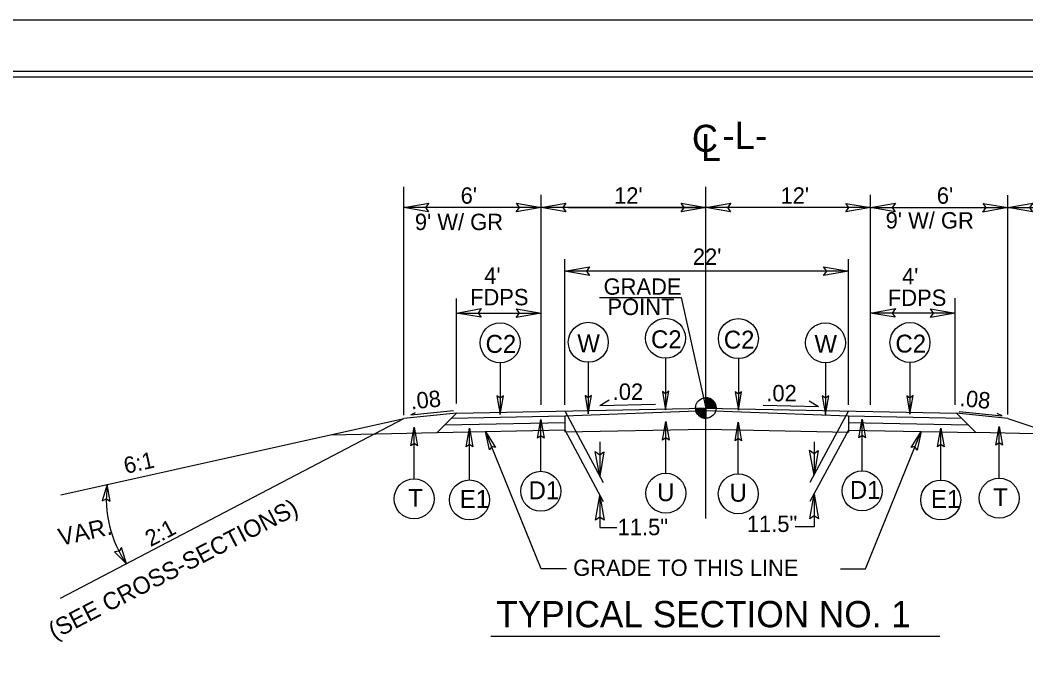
# Model space of a CAD drawing. Extents: x 1718167 to 1721223, y 797898 to 799800.
# Drawn here: x 1719514 to 1719953.6, y 798840.7 to 799124.4 of the extents above; entities that cross this region are included whole.
import ezdxf

# ---------------------------------------------------------------- set-up
doc = ezdxf.new("R2010")
doc.units = 0
for name, color, linetype in [('Old_Level_1', 7, 'Continuous'), ('Old_Level_2', 7, 'Continuous'), ('Prop Dimension Text', 7, 'Continuous'), ('Prop Terminator CELL', 7, 'Continuous'), ('Sheet Cutting Line CELL', 7, 'Continuous'), ('Sheet Plot Border Inside CELL', 7, 'Continuous'), ('Sheet Plot Border Outside CELL', 7, 'Continuous'), ('Sheet Typical CELL', 7, 'Continuous'), ('Typical ID Circle CELL', 7, 'Continuous'), ('Typical Slope Point Local CELL', 7, 'Continuous'), ('Typical Terminator CELL', 7, 'Continuous'), ('Typical Text Centerline CELL', 7, 'Continuous'), ('Typical Text Grade Point CELL', 7, 'Continuous'), ('Typical Text ID Circle CELL', 7, 'Continuous'), ('Typical Text Label CELL', 7, 'Continuous')]:
    doc.layers.add(name, color=color, linetype=linetype)

# ---------------------------------------------------------------- blocks, each defined once
blk = doc.blocks.new('TERMINATOR')
at = {"layer": 'Typical Terminator CELL'}
blk.add_lwpolyline([(-0.469, 0.081), (0, 0), (-0.471, -0.083), (-0.411, 0)], close=True, dxfattribs=at)

msp = doc.modelspace()

# ---------------------------------------------------------------- linework, layer by layer
at = {"layer": 'Old_Level_1'}
for p, q in [((1719681.71, 798951.59), (1719681.73, 799051.4)), ((1719741.7, 798956.19), (1719741.72, 799047.93)), ((1719885.7, 798956.16), (1719885.72, 799047.9)), ((1719945.7, 798951.89), (1719945.72, 799047.89)), ((1719741.72, 799042.41), (1719681.72, 799042.43)), ((1719813.72, 799042.4), (1719741.72, 799042.41)), ((1719753.72, 799042.41), (1719813.72, 799042.4)), ((1719885.72, 799042.38), (1719813.72, 799042.4)), ((1719885.72, 799042.38), (1720017.84, 799042.36)), ((1719752.01, 798989.24), (1719752.01, 799019.85)), ((1719876.01, 798989.22), (1719876.01, 799019.82)), ((1719876.01, 799014.6), (1719752.01, 799014.63)), ((1719704.7, 798956.67), (1719704.71, 799002.7)), ((1719767.28, 799003.14), (1719802.96, 799003.13)), ((1719802.96, 799003.13), (1719813.7, 798954.76)), ((1719922.7, 798956.15), (1719922.71, 799002.82)), ((1719704.71, 798996.29), (1719741.71, 798996.29)), ((1719922.71, 798996.28), (1719885.71, 798996.29)), ((1719752, 798956.19), (1719752.01, 798989.24)), ((1719876, 798956.16), (1719876.01, 798989.22)), ((1719813.7, 798954.76), (1719813.71, 798959.26)), ((1719752, 798953.47), (1719768.77, 798922.18)), ((1719809.2, 798954.76), (1719813.7, 798954.76)), ((1719813.69, 798950.26), (1719813.7, 798954.76)), ((1719813.7, 798954.76), (1719813.69, 798950.26)), ((1719818.2, 798954.76), (1719813.7, 798954.76)), ((1719876, 798953.46), (1719859.24, 798922.16)), ((1719924.47, 798953.28), (1719943.19, 798951.38)), ((1719704.71, 798952.49), (1719681.7, 798950.17)), ((1719945.7, 798950.2), (1719923.24, 798952.48)), ((1719943.19, 798951.38), (1719941.11, 798952.42)), ((1719945.7, 798950.2), (1720017.82, 798926.14)), ((1719741.69, 798884.42), (1719717.44, 798944.48)), ((1719752, 798945.15), (1719768.76, 798913.86)), ((1719876, 798945.14), (1719859.23, 798913.84)), ((1719883.54, 798884.42), (1719907.79, 798944.48)), ((1719767.32, 798939.93), (1719767.32, 798924.87)), ((1719860.99, 798939.93), (1719860.99, 798925.45)), ((1719767.32, 798916.55), (1719767.32, 798902.47)), ((1719860.99, 798917.13), (1719860.99, 798902.83)), ((1719767.32, 798902.47), (1719774.83, 798902.47)), ((1719860.99, 798902.83), (1719852.72, 798902.83)), ((1719752.74, 798884.42), (1719741.69, 798884.42)), ((1719872.5, 798884.42), (1719883.54, 798884.42))]:
    msp.add_line(p, q, dxfattribs=at)
for points in [[(1719813.75, 798959.26), (1719813.75, 798959.26), (1719813.74, 798954.76)], [(1719813.84, 798959.26), (1719813.83, 798954.76)], [(1719813.93, 798959.25), (1719813.92, 798954.76)], [(1719814.02, 798959.25), (1719814.01, 798954.76)], [(1719814.11, 798959.24), (1719814.1, 798954.76)], [(1719814.2, 798959.23), (1719814.19, 798954.76)], [(1719814.29, 798959.22), (1719814.28, 798954.76)], [(1719814.38, 798959.21), (1719814.37, 798954.76)], [(1719814.47, 798959.2), (1719814.46, 798954.76)], [(1719814.56, 798959.18), (1719814.55, 798954.76)], [(1719814.65, 798959.16), (1719814.64, 798954.76)], [(1719814.74, 798959.14), (1719814.73, 798954.76)], [(1719814.83, 798959.12), (1719814.82, 798954.76)], [(1719814.92, 798959.09), (1719814.91, 798954.76)], [(1719815.01, 798959.07), (1719815, 798954.76)], [(1719815.1, 798959.04), (1719815.09, 798954.76)], [(1719815.19, 798959.01), (1719815.18, 798954.76)], [(1719815.28, 798958.98), (1719815.27, 798954.76)], [(1719815.37, 798958.94), (1719815.36, 798954.76)], [(1719815.46, 798958.9), (1719815.45, 798954.76)], [(1719815.55, 798958.86), (1719815.54, 798954.76)], [(1719815.64, 798958.82), (1719815.63, 798954.76)], [(1719815.73, 798958.78), (1719815.72, 798954.76)], [(1719815.82, 798958.73), (1719815.81, 798954.76)], [(1719815.91, 798958.68), (1719815.9, 798954.76)], [(1719816, 798958.63), (1719815.99, 798954.76)], [(1719816.09, 798958.58), (1719816.08, 798954.76)], [(1719816.18, 798958.52), (1719816.17, 798954.76)], [(1719816.27, 798958.46), (1719816.26, 798954.76)], [(1719816.36, 798958.39), (1719816.35, 798954.76)], [(1719816.45, 798958.33), (1719816.44, 798954.76)], [(1719816.54, 798958.26), (1719816.53, 798954.76)], [(1719816.63, 798958.18), (1719816.62, 798954.76)], [(1719816.72, 798958.1), (1719816.71, 798954.76)], [(1719816.81, 798958.02), (1719816.8, 798954.76)], [(1719816.9, 798957.93), (1719816.89, 798954.76)], [(1719816.98, 798957.84), (1719816.98, 798954.76)], [(1719817.07, 798957.74), (1719817.07, 798954.76)], [(1719817.16, 798957.63), (1719817.16, 798954.76)], [(1719817.25, 798957.52), (1719817.25, 798954.76)], [(1719817.34, 798957.4), (1719817.34, 798954.76)], [(1719809.22, 798954.76), (1719809.22, 798954.27)], [(1719809.31, 798954.76), (1719809.31, 798953.74)], [(1719809.4, 798954.76), (1719809.4, 798953.42)], [(1719809.49, 798954.76), (1719809.49, 798953.15)], [(1719809.58, 798954.76), (1719809.58, 798952.94)], [(1719809.67, 798954.76), (1719809.67, 798952.75)], [(1719809.76, 798954.76), (1719809.76, 798952.58)], [(1719809.85, 798954.76), (1719809.85, 798952.42)], [(1719809.94, 798954.76), (1719809.94, 798952.28)], [(1719810.03, 798954.76), (1719810.03, 798952.15)], [(1719810.12, 798954.76), (1719810.12, 798952.03)], [(1719810.21, 798954.76), (1719810.21, 798951.92)], [(1719810.3, 798954.76), (1719810.3, 798951.81)], [(1719810.39, 798954.76), (1719810.39, 798951.71)], [(1719810.48, 798954.76), (1719810.48, 798951.61)], [(1719810.57, 798954.76), (1719810.57, 798951.52)], [(1719810.66, 798954.76), (1719810.66, 798951.44)], [(1719810.75, 798954.76), (1719810.75, 798951.36)], [(1719810.84, 798954.76), (1719810.84, 798951.28)], [(1719810.93, 798954.76), (1719810.93, 798951.21)], [(1719811.02, 798954.76), (1719811.02, 798951.14)], [(1719811.11, 798954.76), (1719811.11, 798951.08)], [(1719811.2, 798954.76), (1719811.2, 798951.02)], [(1719811.29, 798954.76), (1719811.29, 798950.96)], [(1719811.38, 798954.76), (1719811.38, 798950.9)], [(1719811.47, 798954.76), (1719811.47, 798950.85)], [(1719811.56, 798954.76), (1719811.56, 798950.8)], [(1719811.65, 798954.76), (1719811.65, 798950.75)], [(1719811.74, 798954.76), (1719811.74, 798950.71)], [(1719811.83, 798954.76), (1719811.83, 798950.67)], [(1719811.92, 798954.76), (1719811.92, 798950.63)], [(1719812.01, 798954.76), (1719812.01, 798950.59)], [(1719812.1, 798954.76), (1719812.1, 798950.55)], [(1719812.19, 798954.76), (1719812.19, 798950.52)], [(1719812.28, 798954.76), (1719812.28, 798950.49)], [(1719812.37, 798954.76), (1719812.37, 798950.46)], [(1719812.46, 798954.76), (1719812.46, 798950.44)], [(1719812.55, 798954.76), (1719812.55, 798950.41)], [(1719812.64, 798954.76), (1719812.64, 798950.39)], [(1719812.73, 798954.76), (1719812.73, 798950.37)], [(1719812.82, 798954.76), (1719812.82, 798950.35)], [(1719812.91, 798954.76), (1719812.91, 798950.33)], [(1719813, 798954.76), (1719813, 798950.32)], [(1719813.09, 798954.76), (1719813.09, 798950.3)], [(1719813.18, 798954.76), (1719813.18, 798950.29)], [(1719813.27, 798954.76), (1719813.27, 798950.28)], [(1719813.36, 798954.76), (1719813.36, 798950.27)], [(1719813.45, 798954.76), (1719813.45, 798950.27)], [(1719813.54, 798954.76), (1719813.54, 798950.26)], [(1719813.63, 798954.76), (1719813.63, 798950.26), (1719813.63, 798950.26)], [(1719817.43, 798957.27), (1719817.43, 798954.76)], [(1719817.52, 798957.13), (1719817.52, 798954.76)], [(1719817.61, 798956.98), (1719817.61, 798954.76)], [(1719817.7, 798956.82), (1719817.7, 798954.76)], [(1719817.79, 798956.63), (1719817.79, 798954.76)], [(1719817.88, 798956.42), (1719817.88, 798954.76)], [(1719817.97, 798956.17), (1719817.97, 798954.76)], [(1719818.06, 798955.86), (1719818.06, 798954.76)], [(1719818.15, 798955.4), (1719818.15, 798954.76)]]:
    msp.add_lwpolyline(points, dxfattribs=at)
msp.add_circle((1719813.7, 798954.76), 4.5, dxfattribs=at)
for start, end in [(359.9785, 89.9785), (179.9785, 269.9785)]:
    msp.add_arc((1719813.7, 798954.76), 4.5, start, end, dxfattribs=at)
at = {"layer": 'Old_Level_2'}
for p, q in [((1719767.39, 798955.9), (1719771.47, 798958.36)), ((1719863.01, 798955.32), (1719858.93, 798957.78)), ((1719684.7, 798951.8), (1719703.42, 798953.68)), ((1719767.39, 798955.9), (1719791.68, 798956.39)), ((1719863.01, 798955.32), (1719838.72, 798955.81)), ((1719684.7, 798951.8), (1719686.78, 798952.84))]:
    msp.add_line(p, q, dxfattribs=at)
at = {"layer": 'Prop Dimension Text'}
msp.add_arc((1719601.29, 798914.9), 49.64, 172.5997, 214.6638, dxfattribs=at)
at = {"layer": 'Prop Terminator CELL'}
for points in [[(1719692.52, 799040.56), (1719681.72, 799042.43), (1719692.58, 799044.34), (1719691.2, 799042.42)], [(1719730.92, 799044.28), (1719741.72, 799042.41), (1719730.86, 799040.5), (1719732.24, 799042.42)], [(1719752.52, 799040.55), (1719741.72, 799042.41), (1719752.58, 799044.33), (1719751.2, 799042.41)], [(1719802.92, 799044.26), (1719813.72, 799042.4), (1719802.86, 799040.48), (1719804.24, 799042.4)], [(1719824.52, 799040.54), (1719813.72, 799042.4), (1719824.58, 799044.32), (1719823.2, 799042.4)], [(1719874.92, 799044.25), (1719885.72, 799042.38), (1719874.86, 799040.47), (1719876.24, 799042.39)], [(1719896.52, 799040.52), (1719885.72, 799042.38), (1719896.58, 799044.3), (1719895.2, 799042.38)], [(1719934.92, 799044.23), (1719945.72, 799042.37), (1719934.86, 799040.45), (1719936.24, 799042.37)], [(1719956.52, 799040.51), (1719945.72, 799042.37), (1719956.58, 799044.29), (1719955.2, 799042.37)], [(1719762.81, 799012.76), (1719752.01, 799014.63), (1719762.87, 799016.54), (1719761.49, 799014.62)], [(1719865.21, 799016.46), (1719876.01, 799014.6), (1719865.15, 799012.68), (1719866.53, 799014.6)], [(1719715.51, 798994.43), (1719704.71, 798996.29), (1719715.57, 798998.21), (1719714.19, 798996.29)], [(1719730.91, 798998.15), (1719741.71, 798996.29), (1719730.85, 798994.37), (1719732.23, 798996.29)], [(1719896.51, 798994.42), (1719885.71, 798996.29), (1719896.57, 798998.2), (1719895.19, 798996.28)], [(1719911.91, 798998.14), (1719922.71, 798996.28), (1719911.85, 798994.36), (1719913.23, 798996.28)], [(1719769.17, 798935.67), (1719767.32, 798924.87), (1719765.39, 798935.73), (1719767.31, 798934.35)], [(1719862.85, 798936.25), (1719860.99, 798925.45), (1719859.07, 798936.31), (1719860.99, 798934.93)], [(1719765.47, 798905.75), (1719767.32, 798916.55), (1719769.26, 798905.7), (1719767.33, 798907.07)], [(1719859.15, 798906.33), (1719860.99, 798917.13), (1719862.93, 798906.27), (1719861.01, 798907.65)]]:
    msp.add_lwpolyline(points, close=True, dxfattribs=at)
at = {"layer": 'Sheet Cutting Line CELL'}
msp.add_line((1720550, 799124.37), (1718866, 799124.37), dxfattribs=at)
at = {"layer": 'Sheet Plot Border Inside CELL'}
msp.add_lwpolyline([(1720545.5, 799101.92), (1718879, 799101.92), (1718879, 798046.82), (1720545.5, 798046.82)], close=True, dxfattribs=at)
at = {"layer": 'Sheet Plot Border Outside CELL'}
msp.add_lwpolyline([(1720550, 799124.37), (1718866, 799124.37), (1718866, 798024.37), (1720550, 798024.37)], close=True, dxfattribs=at)
at = {"layer": 'Sheet Typical CELL'}
msp.add_lwpolyline([(1720533, 799099.37), (1719033, 799099.37), (1719033, 798049.37), (1720533, 798049.37)], close=True, dxfattribs=at)
at = {"layer": 'Typical ID Circle CELL'}
for p, q in [((1719796.1, 798976.52), (1719796.1, 798953.93)), ((1719827.92, 798976.36), (1719827.92, 798953.76)), ((1719723.78, 798974.5), (1719723.78, 798951.91)), ((1719762.34, 798974.75), (1719762.34, 798952.15)), ((1719866.01, 798974.54), (1719866.01, 798951.95)), ((1719902.94, 798974.62), (1719902.94, 798952.03)), ((1719741.57, 798927.09), (1719741.57, 798949.68)), ((1719796.22, 798926.23), (1719796.22, 798948.83)), ((1719827.9, 798925.98), (1719827.9, 798948.58)), ((1719882.02, 798927.25), (1719882.02, 798949.85)), ((1719686.18, 798923.79), (1719686.18, 798946.38)), ((1719710.41, 798923.29), (1719710.41, 798945.89)), ((1719916.39, 798923.28), (1719916.39, 798945.88)), ((1719941.93, 798924.08), (1719941.93, 798946.67))]:
    msp.add_line(p, q, dxfattribs=at)
for centre in [(1719796.1, 798985.26), (1719827.92, 798985.1), (1719723.78, 798983.25), (1719762.34, 798983.49), (1719866.01, 798983.28), (1719902.94, 798983.37), (1719741.57, 798918.34), (1719882.02, 798918.51), (1719686.18, 798915.05), (1719710.41, 798914.55), (1719796.22, 798917.49), (1719827.9, 798917.24), (1719916.39, 798914.54), (1719941.93, 798915.33)]:
    msp.add_circle(centre, 8.74, dxfattribs=at)
at = {"layer": 'Typical Slope Point Local CELL'}
for p, q in [((1719704.71, 798952.49), (1719813.7, 798954.76)), ((1719752, 798951.28), (1719813.7, 798953.64)), ((1719813.7, 798954.76), (1719923.24, 798952.48)), ((1719813.7, 798953.64), (1719876, 798951.28)), ((1719531.69, 798871.59), (1719681.7, 798950.17)), ((1719531.7, 798916.76), (1719681.7, 798950.17)), ((1719704.71, 798952.49), (1719696.21, 798943.99)), ((1719702.47, 798950.25), (1719752, 798951.28)), ((1719752, 798951.28), (1719752, 798944.28)), ((1719876, 798951.28), (1719876, 798944.27)), ((1719876, 798951.28), (1719925.46, 798950.25)), ((1719923.24, 798952.48), (1719931.73, 798943.98)), ((1719696.21, 798943.99), (1719752, 798945.15)), ((1719699.6, 798947.38), (1719752, 798948.47)), ((1719752, 798944.28), (1719813.7, 798945.56)), ((1719813.7, 798945.56), (1719876, 798944.27)), ((1719876, 798948.46), (1719928.34, 798947.37)), ((1719876, 798945.14), (1719931.73, 798943.98)), ((1719649.61, 798943.03), (1719696.21, 798943.99)), ((1719966.5, 798943.26), (1719931.73, 798943.98))]:
    msp.add_line(p, q, dxfattribs=at)
at = {"layer": 'Typical Text Centerline CELL'}
msp.add_line((1719813.69, 798906.41), (1719813.72, 799051.44), dxfattribs=at)
at = {"layer": 'Typical Text Label CELL'}
msp.add_line((1719719.7, 798855), (1719915.97, 798855), dxfattribs=at)

# ---------------------------------------------------------------- block references
at = {"layer": 'Prop Dimension Text', "yscale": -22.093150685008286}
for p, xscale, rotation in [((1719552.06, 798921.29), 15.392576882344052, 86.31361772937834), ((1719560.45, 798886.66), 15.392576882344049, -59.199412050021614)]:
    msp.add_blockref('TERMINATOR', p, dxfattribs=dict(at, xscale=xscale, rotation=rotation))
at = {"layer": 'Typical Terminator CELL', "xscale": 17.2740059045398}
for p, yscale, rotation in [((1719796.1, 798953.93), -17.2740059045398, -90), ((1719827.92, 798953.76), -17.2740059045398, -90), ((1719723.78, 798951.91), -17.2740059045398, -90), ((1719762.34, 798952.15), -17.2740059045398, -90), ((1719866.01, 798951.95), -17.2740059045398, -90), ((1719902.94, 798952.03), -17.2740059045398, -90), ((1719741.57, 798949.68), 17.2740059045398, 90), ((1719796.22, 798948.83), 17.2740059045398, 90), ((1719827.9, 798948.58), 17.2740059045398, 90), ((1719882.02, 798949.85), 17.2740059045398, 90), ((1719686.18, 798946.38), 17.2740059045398, 90), ((1719710.41, 798945.89), 17.2740059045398, 90), ((1719717.44, 798944.48), 17.2740059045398, 111.98724998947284), ((1719907.79, 798944.48), 17.2740059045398, 68.01275001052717), ((1719916.39, 798945.88), 17.2740059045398, 90), ((1719941.93, 798946.67), 17.2740059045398, 90)]:
    msp.add_blockref('TERMINATOR', p, dxfattribs=dict(at, yscale=yscale, rotation=rotation))

# ---------------------------------------------------------------- texts
at = {"layer": 'Old_Level_1'}
for s, height, rotation, p in [("6'", 7.161, 359.988, (1719706.53, 799044.09)), ("12'", 7.161, 359.988, (1719773.6, 799044.09)), ("12'", 7.161, 359.988, (1719846.35, 799044.09)), ("6'", 7.161, 359.988, (1719914.68, 799044.09)), ("9' W/ GR", 7.161, 359.988, (1719686.52, 799032.56)), ("9' W/ GR", 7.161, 359.988, (1719892.31, 799033.23)), ("22'", 7.161, 359.988, (1719808.03, 799017.35)), (" 4' ", 7.161, 359.988, (1719714.17, 799009.05)), (" 4' ", 7.161, 359.9878, (1719896.8, 799008.77)), ('FDPS', 7.161, 359.988, (1719710.65, 798999.67)), ('FDPS', 7.161, 359.9878, (1719893.28, 798999.39)), ('11.5"', 7.161, 359.988, (1719775.15, 798899.15)), ('11.5"', 7.161, 359.988, (1719831.63, 798900.56)), ('GRADE TO THIS LINE', 7.1614, 359.988, (1719755.74, 798881.36))]:
    msp.add_text(s, height=height, rotation=rotation, dxfattribs=at).set_placement(p)
at = {"layer": 'Old_Level_2'}
for rotation, p in [(5.7484, (1719684.96, 798954.12)), (354.2008, (1719924.46, 798955.68))]:
    msp.add_text('.08 ', height=7.161, rotation=rotation, dxfattribs=at).set_placement(p)
at = {"layer": 'Prop Dimension Text'}
for s, p in [('GRADE', (1719769.02, 799004.28)), ('POINT', (1719770.71, 798995.42)), ('.02', (1719773.01, 798958.32)), ('.02', (1719840.15, 798957.67))]:
    msp.add_text(s, height=7.161, rotation=359.988, dxfattribs=at).set_placement(p)
at = {"layer": 'Typical Slope Point Local CELL'}
for s, height, rotation, p in [('6:1', 7.161, 12.559, (1719560.15, 798925.93)), ('(SEE CROSS-SECTIONS)', 7.5588, 27.2392, (1719528.86, 798853.37)), ('VAR. ', 7.559, 12.559, (1719531.61, 798894.44)), ('2:1', 7.161, 27.6461, (1719570.99, 798893.91))]:
    msp.add_text(s, height=height, rotation=rotation, dxfattribs=at).set_placement(p)
at = {"layer": 'Typical Text Centerline CELL'}
msp.add_text('C', height=11.82, dxfattribs=at).set_placement((1719807.62, 799066.79))
msp.add_text('L', height=11.82, rotation=359.9469, dxfattribs=at).set_placement((1719811.55, 799062.75))
at = {"layer": 'Typical Text Grade Point CELL'}
msp.add_text('-L-', height=12, dxfattribs=at).set_placement((1719820.92, 799067.99))
at = {"layer": 'Typical Text ID Circle CELL'}
for s, height, p in [('C2', 7.826, (1719789.75, 798980.9)), ('C2', 7.826, (1719821.57, 798980.74)), ('C2', 7.826, (1719717.43, 798978.88)), ('W', 7.83, (1719757.53, 798979.13)), ('W', 7.83, (1719861.19, 798978.92)), ('C2', 7.826, (1719896.59, 798979)), ('D1', 7.826, (1719736.23, 798914.88)), ('D1', 7.826, (1719876.68, 798915.04)), ('T', 7.83, (1719683.56, 798911.58)), ('E1', 7.826, (1719706.13, 798911.09)), ('U', 7.83, (1719792.4, 798914.03)), ('U', 7.83, (1719824.08, 798913.78)), ('E1', 7.826, (1719912.11, 798911.08)), ('T', 7.83, (1719939.32, 798911.87))]:
    msp.add_text(s, height=height, dxfattribs=at).set_placement(p)
at = {"layer": 'Typical Text Label CELL'}
msp.add_text('TYPICAL SECTION NO. 1', height=11.5, dxfattribs=at).set_placement((1719722.12, 798858.88))

doc.saveas('drawing.dxf')
